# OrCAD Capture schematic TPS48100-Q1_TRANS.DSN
size B
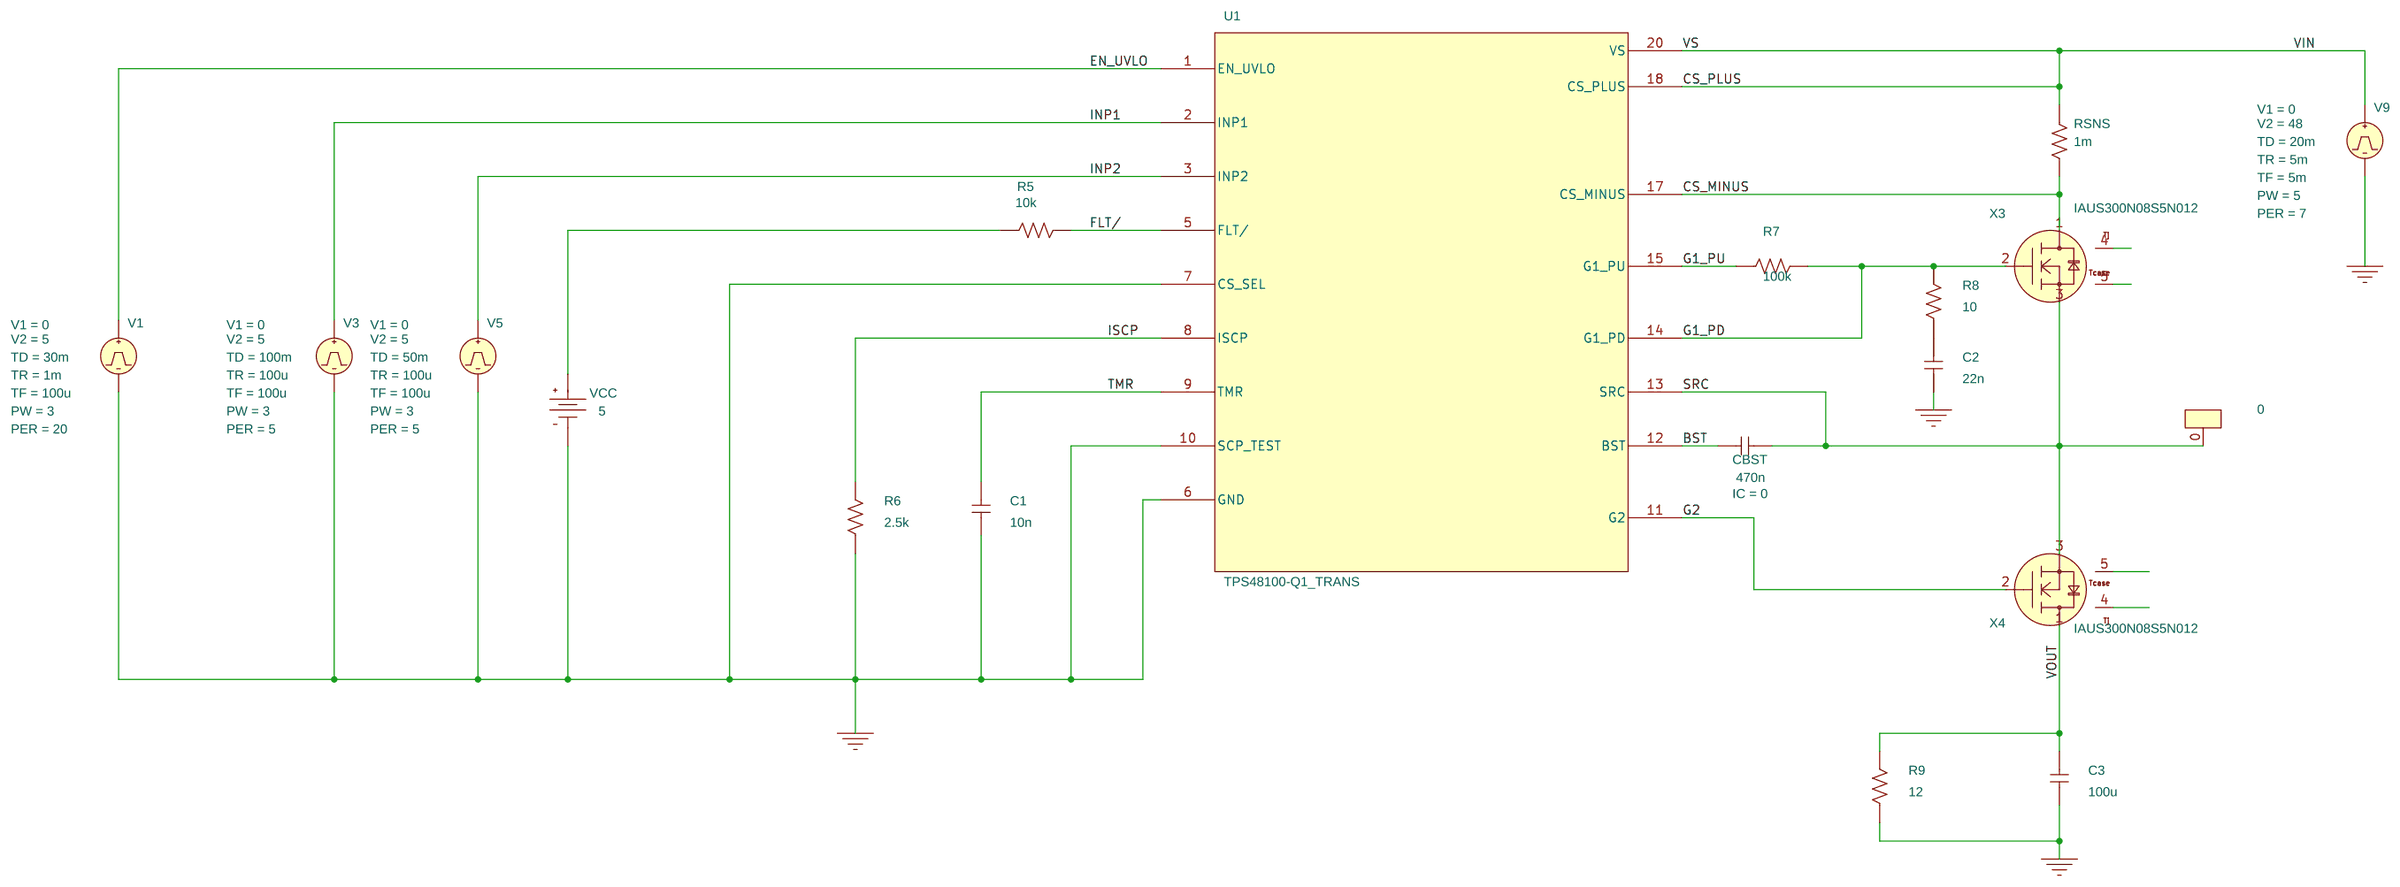
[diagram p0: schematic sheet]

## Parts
C1  10n  [RAD/CK05]
C2  22n  [RAD/CK05]
C3  100u  [RAD/CK05]
CBST  470n  [RAD/CK05]
IC1  0
R5  10k  [AX/RC05]
R6  2.5k  [AX/RC05]
R7  100k  [AX/RC05]
R8  10  [AX/RC05]
R9  12  [AX/RC05]
RSNS  1m  [AX/RC05]
U1  TPS48100-Q1_TRANS
V1  VPULSE
V3  VPULSE
V5  VPULSE
V9  VPULSE
VCC  VDC
X3  IAUS300N08S5N012
X4  IAUS300N08S5N012

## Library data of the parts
C1-C3 = C
CBST = C: IC: 0
IC1 = IC1
R5-R9 RSNS = R
U1 = TPS48100-Q1_TRANS: PSpiceTemplate: X^@REFDES  %BST %CS_MINUS %CS_PLUS %CS_SEL %EN_UVLO %FLT/ %G1_PD %G1_PU %G2 %GND %INP1 %INP2 %ISCP %SCP_TEST %SRC %TMR %VS @MODEL
V1 = VPULSE: PER: 20; PW: 3; TD: 30m; TF: 100u; TR: 1m; V1: 0; V2: 5
V3 = VPULSE: PER: 5; PW: 3; TD: 100m; TF: 100u; TR: 100u; V1: 0; V2: 5
V5 = VPULSE: PER: 5; PW: 3; TD: 50m; TF: 100u; TR: 100u; V1: 0; V2: 5
V9 = VPULSE: PER: 7; PW: 5; TD: 20m; TF: 5m; TR: 5m; V1: 0; V2: 48
VCC = VDC: DC: 5
X3 X4 = IAUS300N08S5N012

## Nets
0: C1.1 C2.1 C3.1 R6.1 R9.1 U1.6(GND) U1.7(CS_SEL) U1.10(SCP_TEST) V1.2(-) V3.2(-) V5.2(-) V9.2(-) VCC.1(-)
BST: CBST.1 U1.12(BST)
CS_MINUS: RSNS.2 U1.17(CS_MINUS) X3.1(drain)
CS_PLUS: RSNS.1 U1.18(CS_PLUS) U1.20(VS) V9.1(+)
EN_UVLO: U1.1(EN_UVLO) V1.1(+)
FLT/: R5.2 U1.5(FLT/)
G1_PD: R7.2 R8.2 U1.14(G1_PD) X3.2(gate)
G1_PU: R7.1 U1.15(G1_PU)
G2: U1.11(G2) X4.2(gate)
INP1: U1.2(INP1) V3.1(+)
INP2: U1.3(INP2) V5.1(+)
ISCP: R6.2 U1.8(ISCP)
SRC: CBST.2 IC1.0(+) U1.13(SRC) X3.3(source) X4.3(source)
TMR: C1.2 U1.9(TMR)
VOUT: C3.2 R9.2 X4.1(drain)
N16694038: R5.1 VCC.0(+)
N16705346: C2.2 R8.1

Not connected (* = marked no-connect by the designer): X3 4(Tj) 5(Tcase); X4 4(Tj) 5(Tcase)
